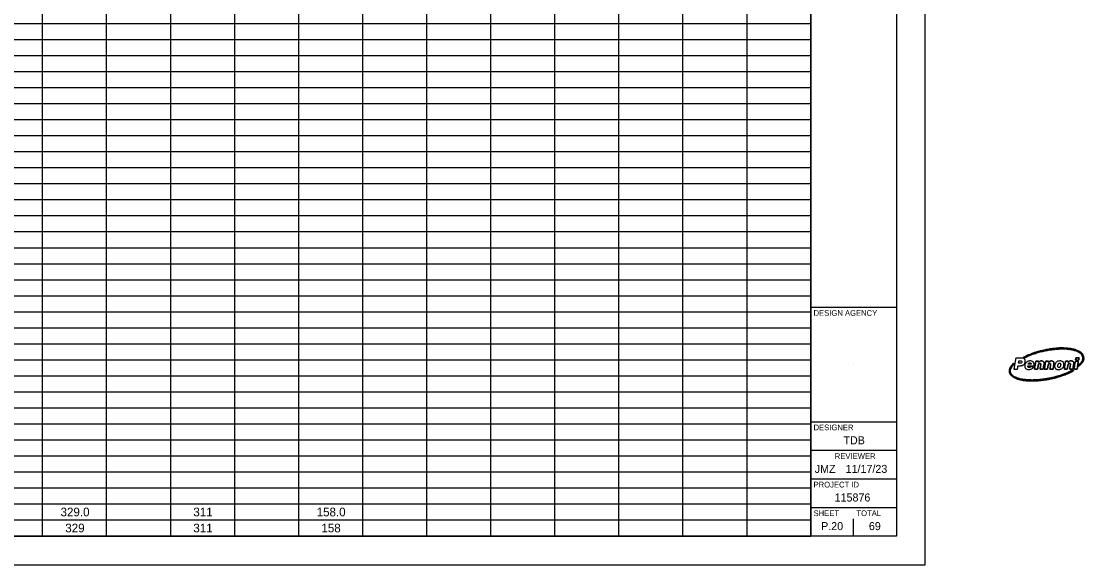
# Model space of a CAD drawing. Extents: x -43.4 to 36.7, y 0 to 22.
# Drawn here: x 18.07 to 36.65, y -0.02 to 9.47 of the extents above; entities that cross this region are included whole.
import ezdxf

# ---------------------------------------------------------------- set-up
doc = ezdxf.new("R2010")
doc.units = 0
for name, color, linetype in [('SH_Border', 7, 'Continuous'), ('SH_Cut_Line', 7, 'Continuous'), ('SH_Data', 7, 'Continuous'), ('SH_Text', 7, 'Continuous')]:
    doc.layers.add(name, color=color, linetype=linetype)

msp = doc.modelspace()

# ---------------------------------------------------------------- linework, layer by layer
at = {"layer": 'SH_Border'}
for p, q in [((31.876, 0.475), (31.876, 21.475)), ((31.876, 4.475), (33.376, 4.475)), ((35.731, 3.478), (35.68, 3.478)), ((31.876, 2.475), (33.376, 2.475)), ((31.876, 1.975), (33.376, 1.975)), ((31.876, 1.475), (33.376, 1.475)), ((31.876, 0.975), (33.376, 0.975))]:
    msp.add_line(p, q, dxfattribs=at)
msp.add_lwpolyline([(1.376, 21.475), (33.376, 21.475), (33.376, 0.475), (1.376, 0.475)], close=True, dxfattribs=at)
for points, degree in [([(35.59, 3.596), (35.597, 3.594), (35.603, 3.591), (35.609, 3.59), (35.611, 3.589), (35.614, 3.589), (35.616, 3.59), (35.644, 3.604), (35.673, 3.618), (35.702, 3.63), (35.743, 3.648), (35.785, 3.663), (35.828, 3.676), (35.87, 3.689), (35.913, 3.7), (35.956, 3.709), (35.995, 3.718), (36.035, 3.726), (36.076, 3.731), (36.108, 3.735), (36.14, 3.739), (36.172, 3.742), (36.197, 3.744), (36.222, 3.745), (36.248, 3.746), (36.303, 3.748), (36.358, 3.745), (36.412, 3.737), (36.442, 3.733), (36.471, 3.727), (36.5, 3.717), (36.535, 3.706), (36.569, 3.692), (36.597, 3.666), (36.612, 3.653), (36.624, 3.636), (36.629, 3.616), (36.634, 3.599), (36.635, 3.582), (36.632, 3.564), (36.629, 3.544), (36.619, 3.527), (36.606, 3.511), (36.594, 3.496), (36.58, 3.483), (36.566, 3.47), (36.564, 3.469), (36.563, 3.467), (36.562, 3.465), (36.561, 3.46), (36.56, 3.454), (36.559, 3.448), (36.558, 3.446), (36.558, 3.444), (36.558, 3.44), (36.582, 3.46), (36.604, 3.48), (36.623, 3.504), (36.632, 3.515), (36.64, 3.528), (36.645, 3.541), (36.652, 3.56), (36.652, 3.579), (36.65, 3.598), (36.646, 3.633), (36.63, 3.66), (36.604, 3.683), (36.58, 3.703), (36.552, 3.716), (36.523, 3.727), (36.486, 3.741), (36.447, 3.749), (36.408, 3.754), (36.373, 3.759), (36.338, 3.762), (36.303, 3.763), (36.247, 3.765), (36.19, 3.762), (36.134, 3.756), (36.103, 3.752), (36.073, 3.748), (36.042, 3.743), (35.997, 3.736), (35.952, 3.727), (35.907, 3.715), (35.847, 3.7), (35.787, 3.682), (35.729, 3.66), (35.688, 3.644), (35.648, 3.626), (35.609, 3.606), (35.603, 3.603), (35.597, 3.6), (35.59, 3.596)], 3), ([(35.59, 3.596), (35.597, 3.6), (35.603, 3.603), (35.609, 3.606), (35.648, 3.626), (35.688, 3.644), (35.729, 3.66), (35.787, 3.682), (35.847, 3.7), (35.907, 3.715), (35.952, 3.727), (35.997, 3.736), (36.042, 3.743), (36.073, 3.748), (36.103, 3.752), (36.134, 3.756), (36.19, 3.762), (36.247, 3.765), (36.303, 3.763), (36.338, 3.762), (36.373, 3.759), (36.408, 3.754), (36.447, 3.749), (36.486, 3.741), (36.523, 3.727), (36.552, 3.716), (36.58, 3.703), (36.604, 3.683), (36.63, 3.66), (36.646, 3.633), (36.65, 3.598), (36.652, 3.579), (36.652, 3.56), (36.645, 3.541), (36.64, 3.528), (36.632, 3.515), (36.623, 3.504), (36.604, 3.48), (36.582, 3.46), (36.558, 3.44), (36.558, 3.444), (36.558, 3.446), (36.559, 3.448), (36.56, 3.454), (36.561, 3.46), (36.562, 3.465), (36.563, 3.467), (36.564, 3.469), (36.566, 3.47), (36.58, 3.483), (36.594, 3.496), (36.606, 3.511), (36.619, 3.527), (36.629, 3.544), (36.632, 3.564), (36.635, 3.582), (36.634, 3.599), (36.629, 3.616), (36.624, 3.636), (36.612, 3.653), (36.597, 3.666), (36.569, 3.692), (36.535, 3.706), (36.5, 3.717), (36.471, 3.727), (36.442, 3.733), (36.412, 3.737), (36.358, 3.745), (36.303, 3.748), (36.248, 3.746), (36.222, 3.745), (36.197, 3.744), (36.172, 3.742), (36.14, 3.739), (36.108, 3.735), (36.076, 3.731), (36.035, 3.726), (35.995, 3.718), (35.956, 3.709), (35.913, 3.7), (35.87, 3.689), (35.828, 3.676), (35.785, 3.663), (35.743, 3.648), (35.702, 3.63), (35.673, 3.618), (35.644, 3.604), (35.616, 3.59), (35.614, 3.589), (35.611, 3.589), (35.609, 3.59), (35.603, 3.591), (35.597, 3.594), (35.59, 3.596)], 3), ([(35.601, 3.577), (35.589, 3.583), (35.575, 3.585), (35.562, 3.585), (35.53, 3.586), (35.498, 3.585), (35.466, 3.586), (35.464, 3.586), (35.463, 3.585), (35.463, 3.583), (35.459, 3.561), (35.455, 3.54), (35.452, 3.518), (35.446, 3.484), (35.44, 3.449), (35.433, 3.414), (35.432, 3.407), (35.431, 3.399), (35.43, 3.392)], 3), ([(35.503, 3.452), (35.511, 3.452), (35.517, 3.452), (35.524, 3.452), (35.537, 3.452), (35.55, 3.452), (35.563, 3.455), (35.58, 3.458), (35.595, 3.465), (35.607, 3.477), (35.621, 3.493), (35.628, 3.512), (35.628, 3.534), (35.628, 3.553), (35.62, 3.568), (35.601, 3.577)], 3), ([(35.511, 3.497), (35.513, 3.511), (35.516, 3.525), (35.518, 3.538), (35.518, 3.539), (35.52, 3.54), (35.52, 3.54), (35.532, 3.54), (35.543, 3.542), (35.555, 3.538), (35.565, 3.535), (35.569, 3.529), (35.567, 3.518)], 3), ([(35.783, 3.483), (35.779, 3.508), (35.766, 3.525), (35.742, 3.532), (35.729, 3.537), (35.715, 3.537), (35.702, 3.536), (35.68, 3.533), (35.66, 3.524), (35.645, 3.507), (35.631, 3.493), (35.623, 3.475), (35.621, 3.454), (35.618, 3.425), (35.63, 3.401), (35.659, 3.392), (35.675, 3.387), (35.691, 3.387), (35.708, 3.389), (35.725, 3.391), (35.742, 3.397), (35.755, 3.409), (35.763, 3.416), (35.77, 3.424), (35.774, 3.434)], 3), ([(35.788, 3.391), (35.789, 3.39), (35.79, 3.39), (35.79, 3.39), (35.807, 3.39), (35.824, 3.39), (35.841, 3.39), (35.844, 3.39), (35.844, 3.392), (35.845, 3.393), (35.846, 3.401), (35.847, 3.41), (35.849, 3.418), (35.852, 3.435), (35.855, 3.453), (35.858, 3.471), (35.86, 3.48), (35.865, 3.488), (35.875, 3.49), (35.888, 3.494), (35.902, 3.491), (35.899, 3.472), (35.898, 3.457), (35.895, 3.443), (35.893, 3.429), (35.89, 3.416), (35.888, 3.404), (35.886, 3.391), (35.887, 3.39), (35.887, 3.39), (35.888, 3.39), (35.905, 3.39), (35.922, 3.39), (35.939, 3.39), (35.941, 3.39), (35.942, 3.392), (35.942, 3.394), (35.946, 3.418), (35.95, 3.441), (35.954, 3.465), (35.957, 3.478), (35.959, 3.49), (35.957, 3.502), (35.955, 3.518), (35.946, 3.53), (35.93, 3.533), (35.908, 3.539), (35.889, 3.535), (35.871, 3.52), (35.868, 3.517), (35.864, 3.513), (35.86, 3.51), (35.861, 3.517), (35.862, 3.524), (35.864, 3.532), (35.847, 3.532), (35.831, 3.532), (35.815, 3.531), (35.814, 3.531), (35.813, 3.53), (35.813, 3.529), (35.812, 3.525), (35.811, 3.521), (35.81, 3.516), (35.805, 3.486), (35.8, 3.455), (35.794, 3.425), (35.792, 3.413), (35.79, 3.402), (35.788, 3.391)], 3), ([(35.788, 3.391), (35.79, 3.402), (35.792, 3.413), (35.794, 3.425), (35.8, 3.455), (35.805, 3.486), (35.81, 3.516), (35.811, 3.521), (35.812, 3.525), (35.813, 3.529), (35.813, 3.53), (35.814, 3.531), (35.815, 3.531), (35.831, 3.532), (35.847, 3.532), (35.864, 3.532), (35.862, 3.524), (35.861, 3.517), (35.86, 3.51), (35.864, 3.513), (35.868, 3.517), (35.871, 3.52), (35.889, 3.535), (35.908, 3.539), (35.93, 3.533), (35.946, 3.53), (35.955, 3.518), (35.957, 3.502), (35.959, 3.49), (35.957, 3.478), (35.954, 3.465), (35.95, 3.441), (35.946, 3.418), (35.942, 3.394), (35.942, 3.392), (35.941, 3.39), (35.939, 3.39), (35.922, 3.39), (35.905, 3.39), (35.888, 3.39), (35.887, 3.39), (35.887, 3.39), (35.886, 3.391), (35.888, 3.404), (35.89, 3.416), (35.893, 3.429), (35.895, 3.443), (35.898, 3.457), (35.899, 3.472), (35.902, 3.491), (35.888, 3.494), (35.875, 3.49), (35.865, 3.488), (35.86, 3.48), (35.858, 3.471), (35.855, 3.453), (35.852, 3.435), (35.849, 3.418), (35.847, 3.41), (35.846, 3.401), (35.845, 3.393), (35.844, 3.392), (35.844, 3.39), (35.841, 3.39), (35.824, 3.39), (35.807, 3.39), (35.79, 3.39), (35.79, 3.39), (35.789, 3.39), (35.788, 3.391)], 3), ([(35.961, 3.391), (35.962, 3.39), (35.962, 3.39), (35.962, 3.39), (35.98, 3.39), (35.997, 3.39), (36.015, 3.39), (36.016, 3.39), (36.017, 3.392), (36.017, 3.393), (36.02, 3.41), (36.023, 3.427), (36.026, 3.444), (36.028, 3.454), (36.03, 3.465), (36.033, 3.475), (36.037, 3.488), (36.049, 3.494), (36.062, 3.491), (36.068, 3.49), (36.071, 3.486), (36.072, 3.48), (36.073, 3.477), (36.073, 3.474), (36.072, 3.471), (36.071, 3.46), (36.069, 3.448), (36.067, 3.437), (36.064, 3.422), (36.062, 3.406), (36.059, 3.391), (36.059, 3.391), (36.059, 3.39), (36.06, 3.39), (36.077, 3.39), (36.095, 3.39), (36.112, 3.39), (36.113, 3.39), (36.115, 3.392), (36.115, 3.393), (36.119, 3.416), (36.123, 3.438), (36.127, 3.46), (36.129, 3.472), (36.13, 3.484), (36.131, 3.497), (36.131, 3.512), (36.125, 3.525), (36.109, 3.531), (36.088, 3.539), (36.069, 3.537), (36.05, 3.525), (36.044, 3.52), (36.039, 3.515), (36.033, 3.51), (36.034, 3.518), (36.036, 3.524), (36.037, 3.532), (36.02, 3.532), (36.004, 3.532), (35.989, 3.532), (35.986, 3.532), (35.986, 3.53), (35.985, 3.528), (35.981, 3.504), (35.977, 3.48), (35.973, 3.457), (35.969, 3.435), (35.965, 3.413), (35.961, 3.391)], 3), ([(35.961, 3.391), (35.965, 3.413), (35.969, 3.435), (35.973, 3.457), (35.977, 3.48), (35.981, 3.504), (35.985, 3.528), (35.986, 3.53), (35.986, 3.532), (35.989, 3.532), (36.004, 3.532), (36.02, 3.532), (36.037, 3.532), (36.036, 3.524), (36.034, 3.518), (36.033, 3.51), (36.039, 3.515), (36.044, 3.52), (36.05, 3.525), (36.069, 3.537), (36.088, 3.539), (36.109, 3.531), (36.125, 3.525), (36.131, 3.512), (36.131, 3.497), (36.13, 3.484), (36.129, 3.472), (36.127, 3.46), (36.123, 3.438), (36.119, 3.416), (36.115, 3.393), (36.115, 3.392), (36.113, 3.39), (36.112, 3.39), (36.095, 3.39), (36.077, 3.39), (36.06, 3.39), (36.059, 3.39), (36.059, 3.391), (36.059, 3.391), (36.062, 3.406), (36.064, 3.422), (36.067, 3.437), (36.069, 3.448), (36.071, 3.46), (36.072, 3.471), (36.073, 3.474), (36.073, 3.477), (36.072, 3.48), (36.071, 3.486), (36.068, 3.49), (36.062, 3.491), (36.049, 3.494), (36.037, 3.488), (36.033, 3.475), (36.03, 3.465), (36.028, 3.454), (36.026, 3.444), (36.023, 3.427), (36.02, 3.41), (36.017, 3.393), (36.017, 3.392), (36.016, 3.39), (36.015, 3.39), (35.997, 3.39), (35.98, 3.39), (35.962, 3.39), (35.962, 3.39), (35.962, 3.39), (35.961, 3.391)], 3), ([(36.304, 3.483), (36.303, 3.505), (36.292, 3.521), (36.272, 3.529), (36.252, 3.537), (36.232, 3.537), (36.212, 3.533), (36.189, 3.528), (36.169, 3.516), (36.156, 3.495), (36.155, 3.493), (36.154, 3.49), (36.153, 3.488), (36.151, 3.486), (36.15, 3.484), (36.149, 3.482), (36.145, 3.471), (36.142, 3.459), (36.142, 3.447), (36.142, 3.445), (36.142, 3.442), (36.142, 3.44), (36.142, 3.432), (36.144, 3.425), (36.146, 3.419), (36.147, 3.418), (36.147, 3.416), (36.148, 3.415), (36.149, 3.414), (36.149, 3.413), (36.15, 3.412), (36.152, 3.409), (36.155, 3.405), (36.158, 3.402), (36.16, 3.401), (36.162, 3.399), (36.165, 3.398), (36.165, 3.397), (36.166, 3.397), (36.166, 3.397), (36.167, 3.396), (36.169, 3.395), (36.17, 3.395), (36.172, 3.394), (36.174, 3.393), (36.176, 3.392), (36.187, 3.388), (36.198, 3.386), (36.21, 3.386)], 3), ([(36.332, 3.531), (36.324, 3.484), (36.316, 3.438), (36.308, 3.39), (36.326, 3.39), (36.345, 3.39), (36.363, 3.39), (36.366, 3.405), (36.368, 3.419), (36.37, 3.433), (36.373, 3.446), (36.375, 3.459), (36.378, 3.471), (36.381, 3.485), (36.391, 3.492), (36.404, 3.492), (36.413, 3.491), (36.418, 3.487), (36.419, 3.478), (36.419, 3.475), (36.419, 3.472), (36.418, 3.469), (36.415, 3.45), (36.412, 3.431), (36.409, 3.412), (36.407, 3.405), (36.406, 3.398), (36.405, 3.39), (36.424, 3.39), (36.442, 3.39), (36.46, 3.39), (36.461, 3.392), (36.461, 3.393), (36.461, 3.394), (36.465, 3.415), (36.469, 3.437), (36.472, 3.458), (36.475, 3.472), (36.478, 3.485), (36.477, 3.5), (36.475, 3.516), (36.467, 3.528), (36.451, 3.533), (36.426, 3.54), (36.404, 3.534), (36.386, 3.516), (36.384, 3.514), (36.382, 3.512), (36.38, 3.51), (36.38, 3.51), (36.379, 3.51), (36.379, 3.511), (36.38, 3.517), (36.382, 3.524), (36.383, 3.531), (36.366, 3.531), (36.349, 3.531), (36.332, 3.531)], 3), ([(36.332, 3.531), (36.349, 3.531), (36.366, 3.531), (36.383, 3.531), (36.382, 3.524), (36.38, 3.517), (36.379, 3.511), (36.379, 3.51), (36.38, 3.51), (36.38, 3.51), (36.382, 3.512), (36.384, 3.514), (36.386, 3.516), (36.404, 3.534), (36.426, 3.54), (36.451, 3.533), (36.467, 3.528), (36.475, 3.516), (36.477, 3.5), (36.478, 3.485), (36.475, 3.472), (36.472, 3.458), (36.469, 3.437), (36.465, 3.415), (36.461, 3.394), (36.461, 3.393), (36.461, 3.392), (36.46, 3.39), (36.442, 3.39), (36.424, 3.39), (36.405, 3.39), (36.406, 3.398), (36.407, 3.405), (36.409, 3.412), (36.412, 3.431), (36.415, 3.45), (36.418, 3.469), (36.419, 3.472), (36.419, 3.475), (36.419, 3.478), (36.418, 3.487), (36.413, 3.491), (36.404, 3.492), (36.391, 3.492), (36.381, 3.485), (36.378, 3.471), (36.375, 3.459), (36.373, 3.446), (36.37, 3.433), (36.368, 3.419), (36.366, 3.405), (36.363, 3.39), (36.345, 3.39), (36.326, 3.39), (36.308, 3.39), (36.316, 3.438), (36.324, 3.484), (36.332, 3.531)], 3), ([(36.535, 3.392), (36.517, 3.392), (36.498, 3.392), (36.48, 3.392), (36.488, 3.439), (36.496, 3.485), (36.504, 3.532), (36.523, 3.532), (36.541, 3.532), (36.56, 3.532), (36.551, 3.485), (36.543, 3.439), (36.535, 3.392)], 3), ([(36.535, 3.392), (36.543, 3.439), (36.551, 3.485), (36.56, 3.532), (36.541, 3.532), (36.523, 3.532), (36.504, 3.532), (36.496, 3.485), (36.488, 3.439), (36.48, 3.392), (36.498, 3.392), (36.517, 3.392), (36.535, 3.392)], 3), ([(36.57, 3.59), (36.567, 3.578), (36.565, 3.566), (36.563, 3.553), (36.563, 3.553), (36.561, 3.551), (36.56, 3.551), (36.543, 3.551), (36.526, 3.551), (36.508, 3.551), (36.509, 3.561), (36.511, 3.57), (36.512, 3.579), (36.513, 3.581), (36.514, 3.584), (36.514, 3.586), (36.514, 3.59), (36.515, 3.591), (36.519, 3.591), (36.534, 3.59), (36.55, 3.59), (36.565, 3.59), (36.567, 3.59), (36.568, 3.59), (36.57, 3.59)], 3), ([(36.57, 3.59), (36.568, 3.59), (36.567, 3.59), (36.565, 3.59), (36.55, 3.59), (36.534, 3.59), (36.519, 3.591), (36.515, 3.591), (36.514, 3.59), (36.514, 3.586), (36.514, 3.584), (36.513, 3.581), (36.512, 3.579), (36.511, 3.57), (36.509, 3.561), (36.508, 3.551), (36.526, 3.551), (36.543, 3.551), (36.56, 3.551), (36.561, 3.551), (36.563, 3.553), (36.563, 3.553), (36.565, 3.566), (36.567, 3.578), (36.57, 3.59)], 3), ([(36.478, 3.367), (36.478, 3.367), (36.478, 3.368), (36.478, 3.368), (36.468, 3.368), (36.458, 3.368), (36.448, 3.368), (36.445, 3.368), (36.443, 3.367), (36.44, 3.366), (36.403, 3.347), (36.365, 3.33), (36.326, 3.315), (36.268, 3.292), (36.209, 3.273), (36.149, 3.258), (36.106, 3.246), (36.062, 3.237), (36.019, 3.229), (35.994, 3.225), (35.969, 3.221), (35.944, 3.218), (35.919, 3.214), (35.893, 3.211), (35.867, 3.209), (35.843, 3.207), (35.819, 3.205), (35.795, 3.205), (35.767, 3.204), (35.738, 3.203), (35.71, 3.205), (35.679, 3.206), (35.648, 3.208), (35.618, 3.211), (35.579, 3.215), (35.542, 3.223), (35.505, 3.234), (35.474, 3.244), (35.444, 3.257), (35.417, 3.277), (35.4, 3.289), (35.386, 3.304), (35.377, 3.323), (35.365, 3.349), (35.366, 3.375), (35.377, 3.402), (35.386, 3.425), (35.4, 3.445), (35.417, 3.463), (35.422, 3.469), (35.428, 3.475), (35.428, 3.484), (35.428, 3.489), (35.43, 3.495), (35.431, 3.501), (35.429, 3.5), (35.429, 3.5), (35.428, 3.499), (35.419, 3.489), (35.409, 3.48), (35.4, 3.469), (35.38, 3.447), (35.364, 3.423), (35.356, 3.394), (35.351, 3.377), (35.35, 3.36), (35.353, 3.343), (35.358, 3.316), (35.372, 3.294), (35.392, 3.276), (35.415, 3.255), (35.441, 3.241), (35.47, 3.229), (35.517, 3.21), (35.566, 3.2), (35.616, 3.194), (35.647, 3.191), (35.678, 3.189), (35.709, 3.187), (35.752, 3.186), (35.794, 3.186), (35.836, 3.19), (35.87, 3.192), (35.905, 3.196), (35.939, 3.2), (35.969, 3.204), (36, 3.209), (36.031, 3.214), (36.085, 3.224), (36.139, 3.236), (36.192, 3.252), (36.237, 3.264), (36.281, 3.279), (36.325, 3.296), (36.368, 3.313), (36.411, 3.331), (36.451, 3.353), (36.46, 3.357), (36.469, 3.362), (36.478, 3.367)], 3), ([(36.478, 3.367), (36.469, 3.362), (36.46, 3.357), (36.451, 3.353), (36.411, 3.331), (36.368, 3.313), (36.325, 3.296), (36.281, 3.279), (36.237, 3.264), (36.192, 3.252), (36.139, 3.236), (36.085, 3.224), (36.031, 3.214), (36, 3.209), (35.969, 3.204), (35.939, 3.2), (35.905, 3.196), (35.87, 3.192), (35.836, 3.19), (35.794, 3.186), (35.752, 3.186), (35.709, 3.187), (35.678, 3.189), (35.647, 3.191), (35.616, 3.194), (35.566, 3.2), (35.517, 3.21), (35.47, 3.229), (35.441, 3.241), (35.415, 3.255), (35.392, 3.276), (35.372, 3.294), (35.358, 3.316), (35.353, 3.343), (35.35, 3.36), (35.351, 3.377), (35.356, 3.394), (35.364, 3.423), (35.38, 3.447), (35.4, 3.469), (35.409, 3.48), (35.419, 3.489), (35.428, 3.499), (35.429, 3.5), (35.429, 3.5), (35.431, 3.501), (35.43, 3.495), (35.428, 3.489), (35.428, 3.484), (35.428, 3.475), (35.422, 3.469), (35.417, 3.463), (35.4, 3.445), (35.386, 3.425), (35.377, 3.402), (35.366, 3.375), (35.365, 3.349), (35.377, 3.323), (35.386, 3.304), (35.4, 3.289), (35.417, 3.277), (35.444, 3.257), (35.474, 3.244), (35.505, 3.234), (35.542, 3.223), (35.579, 3.215), (35.618, 3.211), (35.648, 3.208), (35.679, 3.206), (35.71, 3.205), (35.738, 3.203), (35.767, 3.204), (35.795, 3.205), (35.819, 3.205), (35.843, 3.207), (35.867, 3.209), (35.893, 3.211), (35.919, 3.214), (35.944, 3.218), (35.969, 3.221), (35.994, 3.225), (36.019, 3.229), (36.062, 3.237), (36.106, 3.246), (36.149, 3.258), (36.209, 3.273), (36.268, 3.292), (36.326, 3.315), (36.365, 3.33), (36.403, 3.347), (36.44, 3.366), (36.443, 3.367), (36.445, 3.368), (36.448, 3.368), (36.458, 3.368), (36.468, 3.368), (36.478, 3.368), (36.478, 3.368), (36.478, 3.367), (36.478, 3.367)], 3), ([(35.43, 3.392), (35.431, 3.392), (35.431, 3.392), (35.432, 3.392), (35.451, 3.392), (35.471, 3.392), (35.49, 3.392), (35.492, 3.392), (35.493, 3.393), (35.493, 3.395), (35.495, 3.406), (35.497, 3.417), (35.499, 3.429), (35.5, 3.437), (35.502, 3.444), (35.503, 3.452)], 3), ([(35.567, 3.518), (35.564, 3.506), (35.555, 3.498), (35.543, 3.497), (35.532, 3.497), (35.522, 3.497), (35.511, 3.497)], 3), ([(35.774, 3.434), (35.757, 3.434), (35.74, 3.434), (35.723, 3.434), (35.722, 3.434), (35.721, 3.433), (35.72, 3.432), (35.716, 3.429), (35.712, 3.425), (35.707, 3.423), (35.691, 3.417), (35.674, 3.426), (35.675, 3.445), (35.675, 3.449), (35.676, 3.45), (35.68, 3.45), (35.712, 3.45), (35.744, 3.45), (35.776, 3.45), (35.778, 3.45), (35.78, 3.45), (35.781, 3.45)], 3), ([(35.68, 3.478), (35.682, 3.49), (35.691, 3.5), (35.704, 3.502), (35.71, 3.503), (35.716, 3.503), (35.721, 3.5), (35.729, 3.496), (35.732, 3.488), (35.731, 3.478)], 3), ([(35.781, 3.45), (35.784, 3.461), (35.784, 3.472), (35.783, 3.483)], 2), ([(36.197, 3.446), (36.198, 3.463), (36.201, 3.476), (36.21, 3.488), (36.215, 3.494), (36.222, 3.498), (36.23, 3.498), (36.239, 3.498), (36.245, 3.495), (36.247, 3.486), (36.248, 3.48), (36.249, 3.473), (36.248, 3.466)], 3), ([(36.248, 3.466), (36.248, 3.456), (36.245, 3.446), (36.239, 3.437), (36.234, 3.427), (36.224, 3.422), (36.213, 3.424), (36.207, 3.425), (36.202, 3.428), (36.2, 3.435), (36.199, 3.439), (36.198, 3.444), (36.197, 3.446)], 3), ([(36.21, 3.386), (36.217, 3.386), (36.225, 3.387), (36.232, 3.388), (36.251, 3.392), (36.268, 3.4), (36.281, 3.414), (36.298, 3.434), (36.306, 3.457), (36.304, 3.483)], 3)]:
    msp.add_open_spline(points, degree=degree, dxfattribs=at)
at = {"layer": 'SH_Cut_Line'}
msp.add_lwpolyline([(-0.124, -0.025), (33.876, -0.025), (33.876, 21.975), (-0.124, 21.975)], close=True, dxfattribs=at)
at = {"layer": 'SH_Data'}
for p, q in [((18.438, 21.475), (18.438, 0.477)), ((19.558, 21.475), (19.558, 0.477)), ((20.678, 21.475), (20.678, 0.477)), ((21.798, 21.475), (21.798, 0.477)), ((22.917, 21.475), (22.917, 0.477)), ((24.037, 21.475), (24.037, 0.477)), ((25.157, 21.475), (25.157, 0.477)), ((26.277, 21.475), (26.277, 0.477)), ((27.397, 21.475), (27.397, 0.477)), ((28.517, 21.475), (28.517, 0.477)), ((29.637, 21.475), (29.637, 0.477)), ((30.757, 21.475), (30.757, 0.477)), ((31.877, 21.475), (31.877, 0.477)), ((1.376, 9.436), (31.877, 9.436)), ((1.376, 9.156), (31.877, 9.156)), ((1.376, 8.876), (31.877, 8.876)), ((1.376, 8.596), (31.877, 8.596)), ((1.376, 8.316), (31.877, 8.316)), ((1.376, 8.036), (31.877, 8.036)), ((1.376, 7.756), (31.877, 7.756)), ((1.376, 7.476), (31.877, 7.476)), ((1.376, 7.196), (31.877, 7.196)), ((1.376, 6.916), (31.877, 6.916)), ((1.376, 6.636), (31.877, 6.636)), ((1.376, 6.356), (31.877, 6.356)), ((1.376, 6.076), (31.877, 6.076)), ((1.376, 5.796), (31.877, 5.796)), ((1.376, 5.516), (31.877, 5.516)), ((1.376, 5.236), (31.877, 5.236)), ((1.376, 4.956), (31.877, 4.956)), ((1.376, 4.676), (31.877, 4.676)), ((1.376, 4.396), (31.877, 4.396)), ((1.376, 4.116), (31.877, 4.116)), ((1.376, 3.836), (31.877, 3.836)), ((1.376, 3.556), (31.877, 3.556)), ((32.626, 3.475), (32.626, 3.475)), ((1.376, 3.276), (31.877, 3.276)), ((1.376, 2.997), (31.877, 2.997)), ((1.376, 2.717), (31.877, 2.717)), ((1.376, 2.437), (31.877, 2.437)), ((1.376, 2.157), (31.877, 2.157)), ((1.376, 1.877), (31.877, 1.877)), ((1.376, 1.597), (31.877, 1.597)), ((1.376, 1.317), (31.877, 1.317)), ((1.376, 1.037), (31.877, 1.037)), ((1.376, 0.757), (31.877, 0.757)), ((32.626, 0.475), (32.626, 0.775)), ((32.251, 0.65), (32.251, 0.65)), ((1.376, 0.477), (31.877, 0.477))]:
    msp.add_line(p, q, dxfattribs=at)

# ---------------------------------------------------------------- texts
for s, height, p in [('DESIGN AGENCY', 0.1, (31.926, 4.325)), ('DESIGNER', 0.1, (31.926, 2.325)), ('TDB', 0.14, (32.449, 2.08)), ('REVIEWER', 0.1, (32.297, 1.825)), ('JMZ', 0.14, (31.947, 1.58)), ('11/17/23', 0.14, (32.487, 1.58)), ('PROJECT ID', 0.1, (31.926, 1.325)), ('115876', 0.14, (32.295, 1.08)), ('SHEET', 0.1, (31.926, 0.825)), ('TOTAL', 0.1, (32.676, 0.825)), ('P.20', 0.14, (32.058, 0.58)), ('69', 0.14, (32.894, 0.58))]:
    msp.add_text(s, height=height, dxfattribs=at).set_placement(p)
at = {"layer": 'SH_Text'}
for s, p in [('329.0', (18.757, 0.821)), ('311', (21.08, 0.821)), ('158.0', (23.236, 0.821)), ('329', (18.84, 0.541)), ('311', (21.08, 0.541)), ('158', (23.319, 0.541))]:
    msp.add_text(s, height=0.1515, dxfattribs=at).set_placement(p)

doc.saveas('drawing.dxf')
